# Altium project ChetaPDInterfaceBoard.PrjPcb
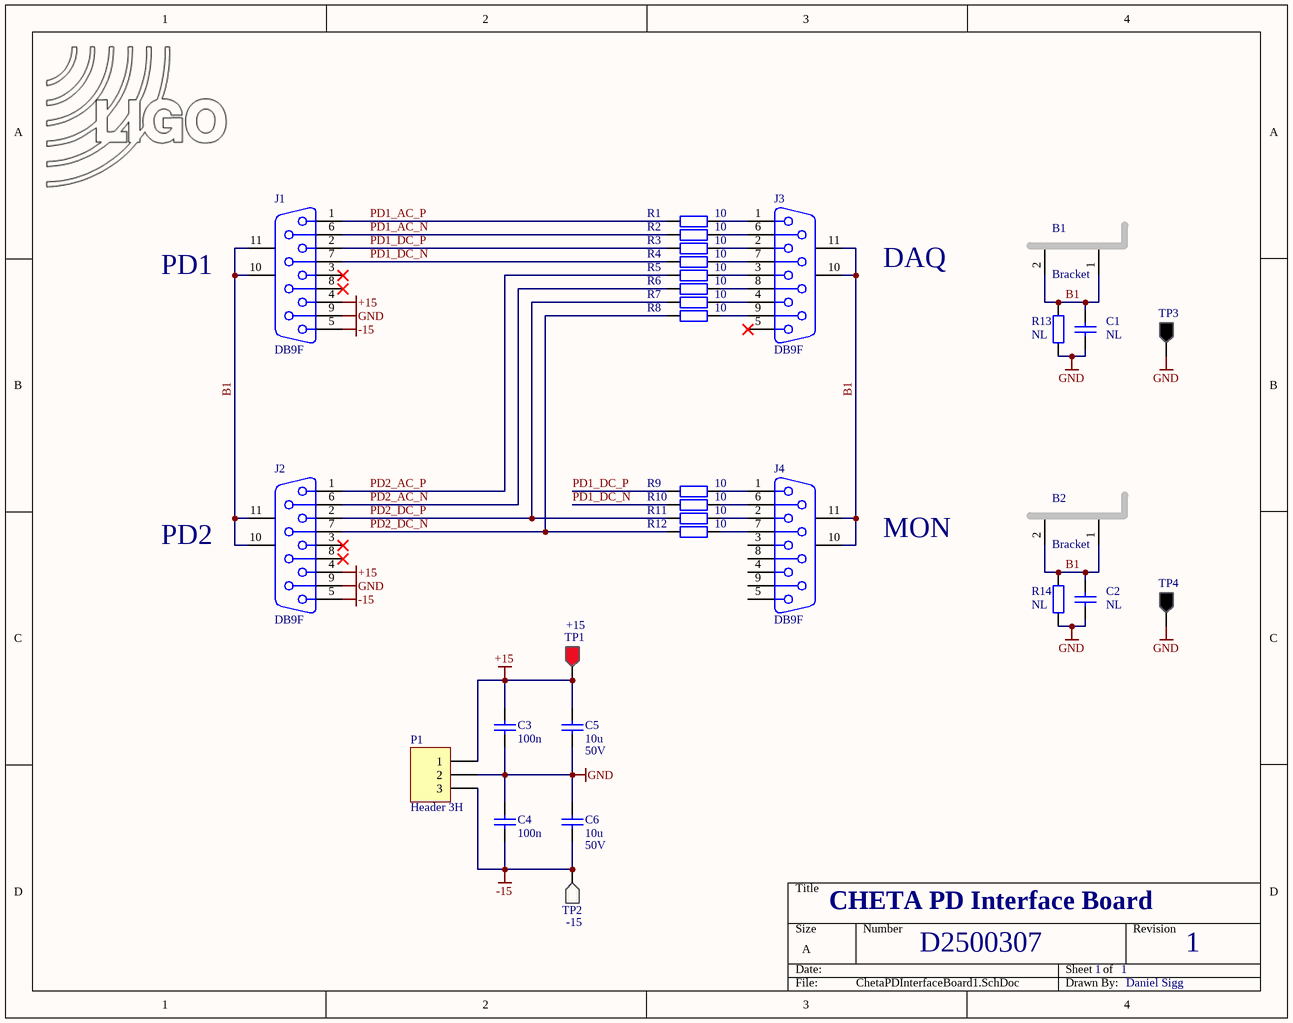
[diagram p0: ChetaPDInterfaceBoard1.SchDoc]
DCC: D2500307; REV: 1
1 sheet, 32 parts. Net scope: global (net labels, ports and power ports of the same name join across sheets).
Board file: ChetaPDInterfaceBoard.PcbDoc

## Sheet ChetaPDInterfaceBoard1.SchDoc
size A; Revision: 1; SheetNumber: 1; SheetTotal: 1

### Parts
B1  Bracket  [Bracket-RA_708]
B2  Bracket  [Bracket-RA_708]
C1  NL  [CC3216-1206]
C2  NL  [CC3216-1206]
C3  100n  [CC2013-0805]
C4  100n  [CC2013-0805]
C5  Voltage Rating: 50V  [CC3225-1210]  (hidden comment: 10u)
C6  Voltage Rating: 50V  [CC3225-1210]  (hidden comment: 10u)
J1  DB9F  [DB9F-RA]
J2  DB9F  [DB9F-RA]
J3  DB9F  [DB9F-RA]
J4  DB9F  [DB9F-RA]
LOGO1  LIGO logo  [LIGO_LOGO]  (value not drawn)  (no BOM)
P1  Header 3H  [Molex_156_RA_3]
R1  10  [CR2012-0805]
R2  10  [CR2012-0805]
R3  10  [CR2012-0805]
R4  10  [CR2012-0805]
R5  10  [CR2012-0805]
R6  10  [CR2012-0805]
R7  10  [CR2012-0805]
R8  10  [CR2012-0805]
R9  10  [CR2012-0805]
R10  10  [CR2012-0805]
R11  10  [CR2012-0805]
R12  10  [CR2012-0805]
R13  NL  [CR2012-0805]
R14  NL  [CR2012-0805]
TP1  +15  [TP1-RED]
TP2  -15  [TP1-WHT]
TP3  GND  [TP1-BLK]  (value not drawn)
TP4  GND  [TP1-BLK]  (value not drawn)

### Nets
+15: C3.2 C5.2 J1.4 J2.4 P1.1 TP1.1
-15: C4.1 C6.1 J1.5 J2.5 P1.3 TP2.1
GND: C1.2 C2.2 C3.1 C4.2 C5.1 C6.2 J1.9 J2.9 P1.2 R13.2 R14.2 TP3.1 TP4.1
B1: B1.1(GND) B1.2(GND) B2.1(GND) B2.2(GND) C1.1 C2.1 J1.10(MH1) J1.11(MH2) J2.10(MH1) J2.11(MH2) J3.10(MH1) J3.11(MH2) J4.10(MH1) J4.11(MH2) R13.1 R14.1
PD1_AC_N: J1.6 R2.1
PD1_AC_P: J1.1 R1.1
PD1_DC_N: J1.7 R4.1 R10.1
PD1_DC_P: J1.2 R3.1 R9.1
PD2_AC_N: J2.6 R6.1
PD2_AC_P: J2.1 R5.1
PD2_DC_N: J2.7 R8.1 R12.1
PD2_DC_P: J2.2 R7.1 R11.1
NetJ3_1: J3.1 R1.2
NetJ3_2: J3.2 R3.2
NetJ3_3: J3.3 R5.2
NetJ3_4: J3.4 R7.2
NetJ3_6: J3.6 R2.2
NetJ3_7: J3.7 R4.2
NetJ3_8: J3.8 R6.2
NetJ3_9: J3.9 R8.2
NetJ4_1: J4.1 R9.2
NetJ4_2: J4.2 R11.2
NetJ4_6: J4.6 R10.2
NetJ4_7: J4.7 R12.2

Not connected (* = marked no-connect by the designer): J1 3* 8*; J2 3* 8*; J3 5*; J4 3 4 5 8 9

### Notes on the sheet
- PD1
- DAQ
- PD2
- MON
- CHETA PD Interface Board
- Daniel Sigg

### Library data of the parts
B1 B2 = Bracket_708: Keystone Electronics right-angle 6-32 steel, 708; Part Number: 36-708-ND
C1 C2 = ChipCap: Capacitor, surface mount; Tolerance: 10%
C3 C4 = ChipCap: Capacitor, surface mount; Part Number: 311-1140-1-ND; Tolerance: 10%
C5 C6 = ChipCap: Capacitor, surface mount; Part Number: 490-4798-1-ND; Tolerance: 10%
J1-J4 = DB9F: Receptacle Assembly, 9 Position, Right Angle, .318 Series; Part Number: A32119-ND
LOGO1 = LIGO_logo
P1 = Header 3H: Header, 3-Pin, Right Angle; Part Number: WM5236-ND
R1-R12 = ChipRes1: Resistor, surface mount; Part Number: RR12Q10DCT-ND; Tolerance: 0.5%
R13 R14 = ChipRes1: Resistor, surface mount; Tolerance: 0.5%
TP1 = TP_POSITIVE: Testpoint, red; Part Number: 36-5005-ND
TP2 = TP_NEGATIVE: Testpoint, white; Part Number: 36-5007-ND
TP3 TP4 = TP_GND: Testpoint, black; Part Number: 36-5006-ND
